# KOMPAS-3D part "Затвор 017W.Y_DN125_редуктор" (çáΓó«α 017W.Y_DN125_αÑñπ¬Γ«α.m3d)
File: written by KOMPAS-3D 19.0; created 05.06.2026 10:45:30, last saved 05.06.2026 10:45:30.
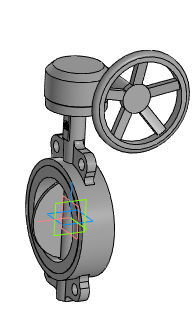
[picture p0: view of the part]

Document properties: Автор: Энергия; Полное имя файла: ..\..\..\3d для проектировщиков\x.x Тип 017W.Y(S) Затвор дисковый поворотный межфланцевый\Затвор 017W.Y(S)_DN50-DN1200_редуктор\Затвор 017W.Y_DN125_редуктор.a3d

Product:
- Part/product: Затвор 017W.Y_DN125_редуктор
    Масса: 12.4056

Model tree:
1. Операция без истории:1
